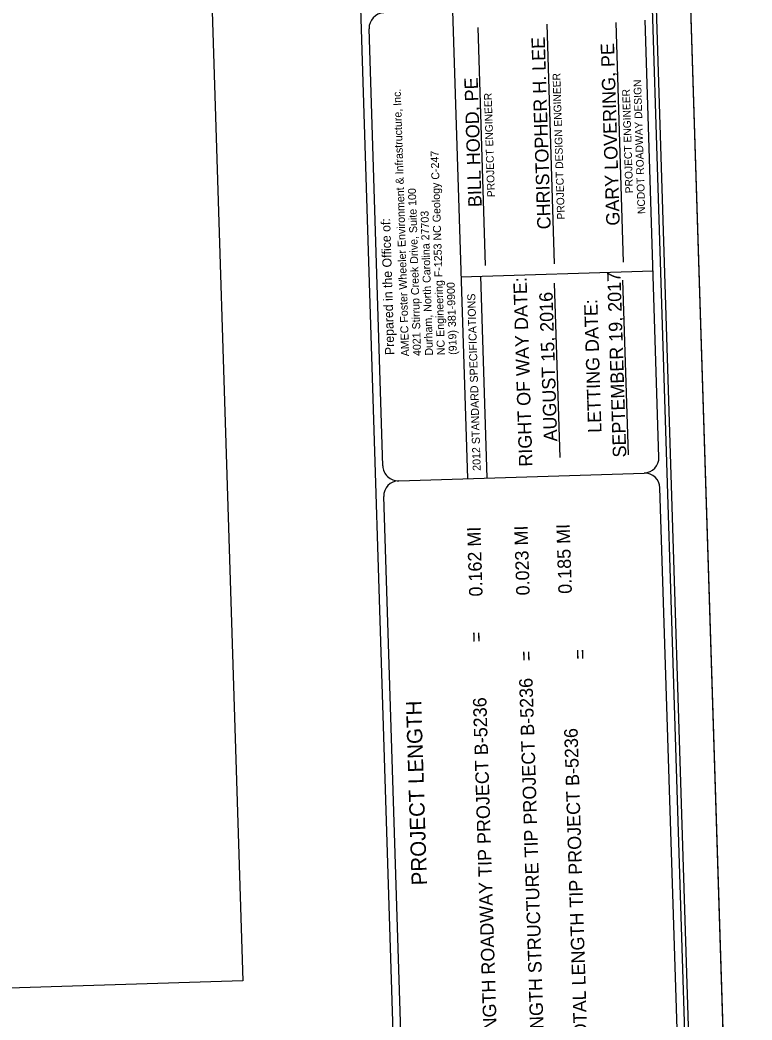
# Model space of a CAD drawing. Extents: x 2308163 to 2335412, y -96774 to 127732.
# Drawn here: x 2326787 to 2327503, y 123493 to 124471 of the extents above; entities that cross this region are included whole.
import ezdxf

# ---------------------------------------------------------------- set-up
doc = ezdxf.new("R2010")
doc.units = 0
for name, color, linetype in [('Sheet Cutting Line CELL', 7, 'Continuous'), ('Sheet Data Text CELL', 7, 'Continuous'), ('Sheet Plan Layout CELL', 7, 'Continuous'), ('Sheet Plot Border Inside CELL', 7, 'Continuous'), ('Sheet Plot Border Outside CELL', 7, 'Continuous'), ('Sheet Title CELL', 7, 'Continuous')]:
    doc.layers.add(name, color=color, linetype=linetype)

msp = doc.modelspace()

# ---------------------------------------------------------------- linework, layer by layer
at = {"layer": 'Sheet Cutting Line CELL'}
msp.add_line((2327502.76, 122587.54), (2327423.2, 125112.28), dxfattribs=at)
at = {"layer": 'Sheet Plan Layout CELL'}
msp.add_lwpolyline([(2326360.15, 123511.38), (2326318.28, 124840.01), (2326963.2, 124860.33), (2327005.07, 123531.7)], close=True, dxfattribs=at)
at = {"layer": 'Sheet Plot Border Inside CELL'}
msp.add_lwpolyline([(2327468.5, 122605.97), (2327389.78, 125104.48), (2325807.91, 125054.63), (2325886.64, 122556.12)], close=True, dxfattribs=at)
at = {"layer": 'Sheet Plot Border Outside CELL'}
msp.add_lwpolyline([(2325774.04, 125060.32), (2325853.59, 122535.57), (2327502.76, 122587.54), (2327423.2, 125112.28)], close=True, dxfattribs=at)
at = {"layer": 'Sheet Title CELL'}
for p, q in [((2327169.46, 122925.21), (2327102.37, 125054.15)), ((2327210.16, 124479.76), (2327224.55, 124022.49)), ((2327377.32, 124234.03), (2327369.93, 124468.29)), ((2327141.99, 124034.89), (2327128.53, 124462.18)), ((2327242.35, 124230.83), (2327235.04, 124463.44)), ((2327309.83, 124232.43), (2327302.45, 124466.69)), ((2327218.34, 124219.71), (2327406.12, 124225.63)), ((2327237.47, 124220.32), (2327243.67, 124023.09)), ((2327309.47, 124213.58), (2327314.85, 124043.04)), ((2327376.32, 124216.29), (2327381.7, 124045.75)), ((2327239.24, 124163.49), (2327239.24, 124163.49)), ((2327312.18, 124128.27), (2327312.18, 124128.27)), ((2327157.46, 124020.37), (2327397.34, 124027.93)), ((2327160.91, 123435.19), (2327142.96, 124004.91))]:
    msp.add_line(p, q, dxfattribs=at)
for points in [[(2327456.93, 122851.72), (2327387.02, 125070.62)], [(2327411.86, 124043.4), (2327398.42, 124470.68)], [(2327430.78, 123443.69), (2327412.82, 124013.41)]]:
    msp.add_lwpolyline(points, dxfattribs=at)
for centre, start, end in [((2327143.46, 124462.66), 91.80479, 181.80479), ((2327396.8, 124042.93), 271.80479, 1.80479), ((2327156.92, 124035.37), 181.80479, 271.80479), ((2327397.75, 124012.94), 1.80479, 91.80479), ((2327157.86, 124005.38), 91.80479, 181.80479)]:
    msp.add_arc(centre, 15, start, end, dxfattribs=at)

# ---------------------------------------------------------------- texts
at = {"layer": 'Sheet Data Text CELL'}
for s, height, rotation, p in [('CHRISTOPHER H. LEE', 13.1251, 91.80479, (2327306.12, 124266.27)), ('GARY LOVERING, PE', 13.1251, 91.80479, (2327373.54, 124269.9)), ('BILL HOOD, PE', 13.1251, 91.80479, (2327238.62, 124288.03)), ('SEPTEMBER 19, 2017', 13.1251, 91.80479, (2327379.97, 124043.32)), ('AUGUST 15, 2016', 13.1251, 91.80479, (2327312.44, 124058.89)), ('0.162 MI', 13.125, 91.80479, (2327239.5, 123907.41)), ('0.023 MI', 13.125, 91.80479, (2327285.54, 123908.49)), ('0.185 MI', 13.125, 91.80479, (2327326.74, 123910.08)), (' =', 13.125, 91.80479, (2327239.98, 123857.79)), (' =', 13.125, 271.80479, (2327275.61, 123858.86)), (' =', 13.125, 271.80479, (2327328.24, 123860.51)), ('LENGTH STRUCTURE TIP PROJECT B-5236', 13.1251, 91.80479, (2327299.72, 123463.28)), ('LENGTH ROADWAY TIP PROJECT B-5236', 13.1251, 91.80479, (2327253.98, 123461.84)), ('TOTAL LENGTH TIP PROJECT B-5236', 13.1251, 91.80479, (2327342.08, 123465.89))]:
    msp.add_text(s, height=height, rotation=rotation, dxfattribs=at).set_placement(p)
at = {"layer": 'Sheet Title CELL'}
for s, height, p in [('PROJECT DESIGN ENGINEER', 7.4992, (2327319.82, 124275.81)), ('NCDOT ROADWAY DESIGN', 7.4992, (2327398.46, 124281.16)), ('AMEC Foster Wheeler Environment & Infrastructure, Inc.', 7.7752, (2327167.68, 124142.05)), ('PROJECT ENGINEER', 7.4992, (2327386.54, 124301.45)), ('PROJECT ENGINEER', 7.4992, (2327251.5, 124297.67)), ('NC Engineering F-1253 NC Geology C-247', 7.7752, (2327202.65, 124143.16)), ('4021 Stirrup Creek Drive, Suite 100 ', 7.7752, (2327179.34, 124142.42)), ('Durham, North Carolina 27703', 7.7752, (2327190.99, 124142.79)), ('Prepared in the Office of:', 8.9991, (2327153.27, 124143.36)), ('(919) 381-9900', 7.7752, (2327214.31, 124143.52)), ('RIGHT OF WAY DATE: ', 13.1247, (2327288.26, 124034.32)), ('2012 STANDARD SPECIFICATIONS', 7.8, (2327237.67, 124030.17)), ('LETTING DATE:', 13.1247, (2327355.73, 124067.44)), ('PROJECT LENGTH', 14.9994, (2327185.14, 123625.2))]:
    msp.add_text(s, height=height, rotation=91.80479, dxfattribs=at).set_placement(p)

doc.saveas('drawing.dxf')
